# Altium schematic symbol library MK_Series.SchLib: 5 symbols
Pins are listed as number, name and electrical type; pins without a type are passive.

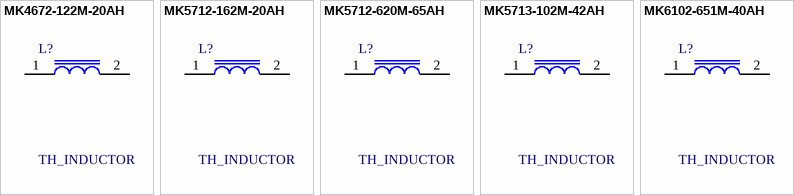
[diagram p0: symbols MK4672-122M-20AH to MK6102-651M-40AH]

## MK4672-122M-20AH
designator L?, comment TH_INDUCTOR
POWER INDUCTOR 20 A, 1.2 mH, 55 mOhms, OD 57.404 mm, HT 50.8 mm; Manufacturer #1: CWS; Current: 20 A; Inductance: 1.2 mH
footprint MK4672-122M-20AH
pins: 1, 2

## MK5712-162M-20AH
designator L?, comment TH_INDUCTOR
POWER INDUCTOR 20 A, 1.6 mH, 60 mOhms, OD 68.072 mm, HT 47.498 mm; Manufacturer #1: CWS; Current: 20 A; Inductance: 1.6 mH
footprint MK5712-162M-20AH
pins: 1, 2

## MK5712-620M-65AH
designator L?, comment TH_INDUCTOR
POWER INDUCTOR 65 A, 62 uH, 2.5 mOhms, OD 70.358 mm, HT 49.022 mm; Manufacturer #1: CWS; Current: 65 A; Inductance: 62 uH
footprint MK5712-620M-65AH
pins: 1, 2

## MK5713-102M-42AH
designator L?, comment TH_INDUCTOR
POWER INDUCTOR 42 A, 1 mH, 27 mOhms, OD 73.406 mm, HT 78.994 mm; Manufacturer #1: CWS; Current: 42 A; Inductance: 1 mH
footprint MK5713-102M-42AH
pins: 1, 2

## MK6102-651M-40AH
designator L?, comment TH_INDUCTOR
POWER INDUCTOR 40 A, 650 uH, 21 mOhms, OD 73.914 mm, HT 65.024 mm; Manufacturer #1: CWS; Current: 40 A; Inductance: 650 uH
footprint MK6102-651M-40AH
pins: 1, 2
